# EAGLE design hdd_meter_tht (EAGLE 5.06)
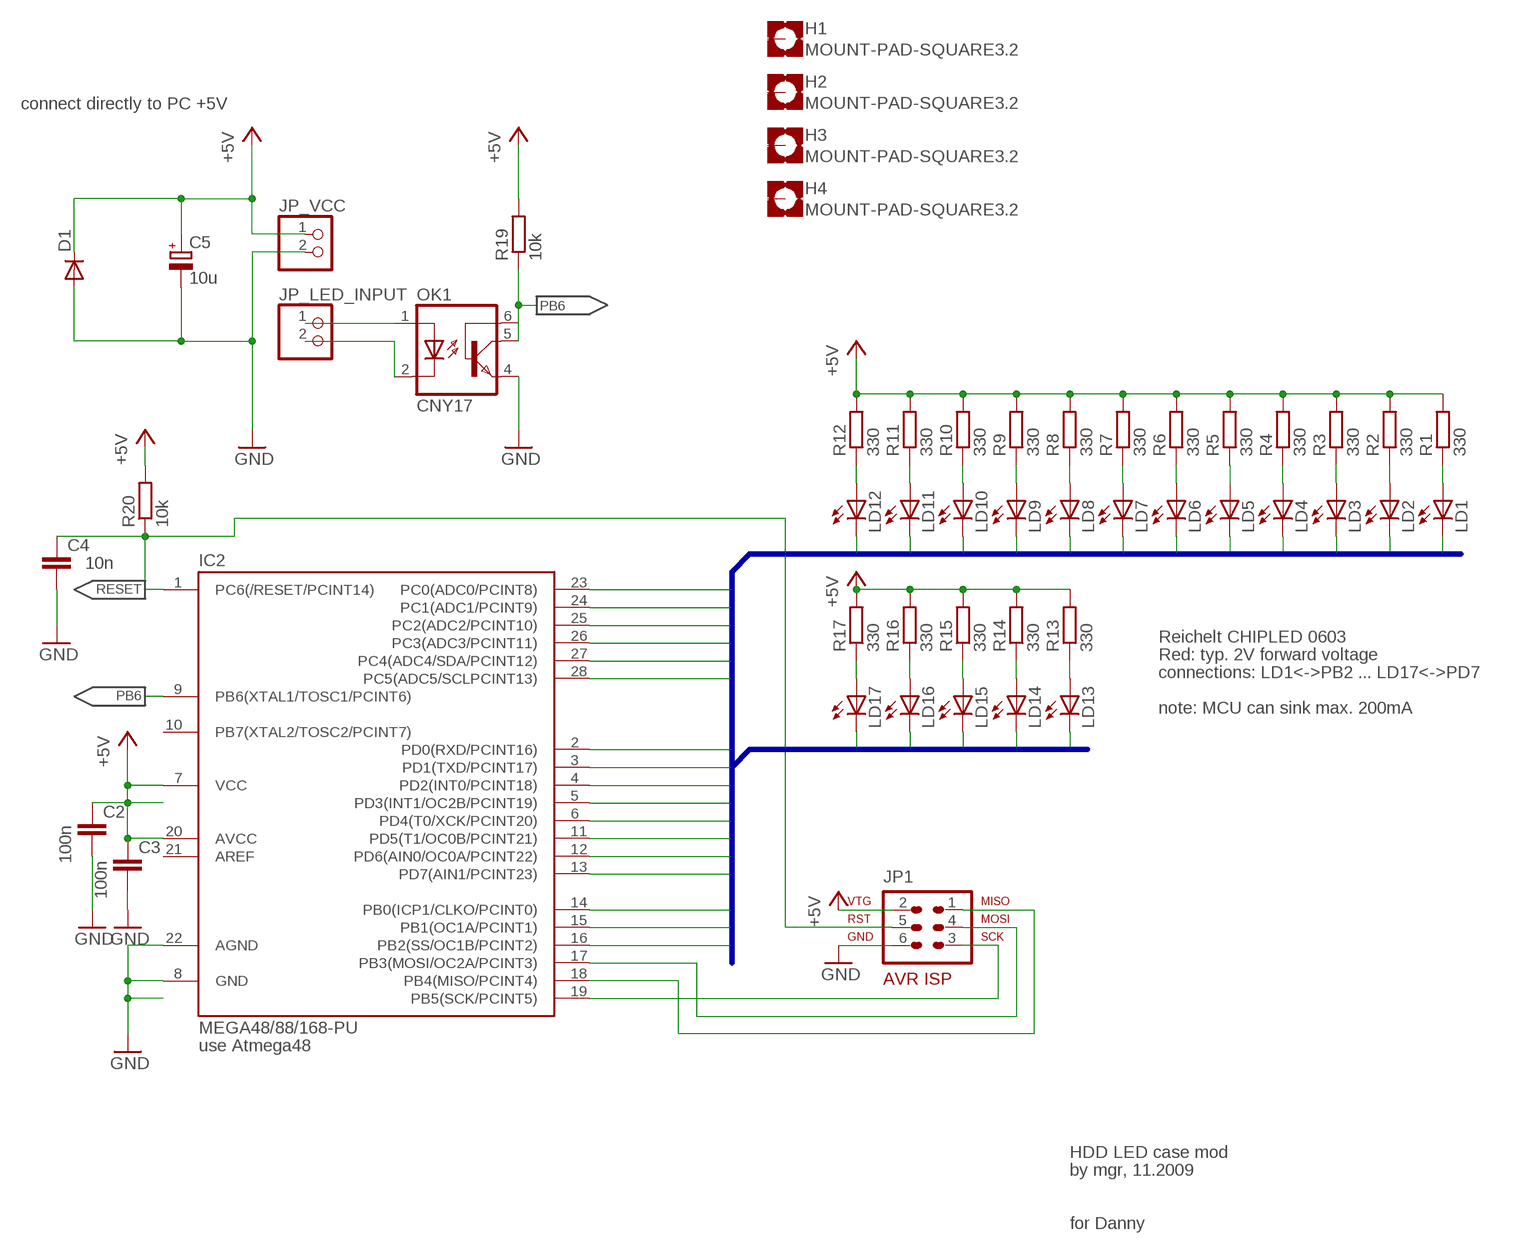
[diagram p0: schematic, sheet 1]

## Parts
C2  100n  C-EU050-024X044  [C050-024X044]
C3  100n  C-EU050-024X044  [C050-024X044]
C4  10n  C-EU050-024X044  [C050-024X044]
C5  10u  CPOL-EUE3.5-10  [E3,5-10]
D1  1N4148DO35-7  [DO35-7]
H1  MOUNT-PAD-SQUARE3.2  [3,2-PAD-SQUARE]
H2  MOUNT-PAD-SQUARE3.2  [3,2-PAD-SQUARE]
H3  MOUNT-PAD-SQUARE3.2  [3,2-PAD-SQUARE]
H4  MOUNT-PAD-SQUARE3.2  [3,2-PAD-SQUARE]
IC2  MEGA48/88/168-PU  [DIL28-3]
JP1  AVR-ISP-6  [AVR-ISP-6]
JP_LED_INPUT  PINHD-1X2  [1X02]
JP_VCC  PINHD-1X2  [1X02]
LD1  LED5MM  [LED5MM]
LD2  LED5MM  [LED5MM]
LD3  LED5MM  [LED5MM]
LD4  LED5MM  [LED5MM]
LD5  LED5MM  [LED5MM]
LD6  LED5MM  [LED5MM]
LD7  LED5MM  [LED5MM]
LD8  LED5MM  [LED5MM]
LD9  LED5MM  [LED5MM]
LD10  LED5MM  [LED5MM]
LD11  LED5MM  [LED5MM]
LD12  LED5MM  [LED5MM]
LD13  LED5MM  [LED5MM]
LD14  LED5MM  [LED5MM]
LD15  LED5MM  [LED5MM]
LD16  LED5MM  [LED5MM]
LD17  LED5MM  [LED5MM]
OK1  CNY17  [DIL06]
R1  330  R-EU_0207/7  [0207/7]
R2  330  R-EU_0207/7  [0207/7]
R3  330  R-EU_0207/7  [0207/7]
R4  330  R-EU_0207/7  [0207/7]
R5  330  R-EU_0207/7  [0207/7]
R6  330  R-EU_0207/7  [0207/7]
R7  330  R-EU_0207/7  [0207/7]
R8  330  R-EU_0207/7  [0207/7]
R9  330  R-EU_0207/7  [0207/7]
R10  330  R-EU_0207/7  [0207/7]
R11  330  R-EU_0207/7  [0207/7]
R12  330  R-EU_0207/7  [0207/7]
R13  330  R-EU_0207/7  [0207/7]
R14  330  R-EU_0207/7  [0207/7]
R15  330  R-EU_0207/7  [0207/7]
R16  330  R-EU_0207/7  [0207/7]
R17  330  R-EU_0207/7  [0207/7]
R19  10k  R-EU_0207/7  [0207/7]
R20  10k  R-EU_0207/7  [0207/7]

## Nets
+5V: C2.1 C3.1 C5.+ D1.C IC2.7(VCC) IC2.20(AVCC) JP1.2 JP_VCC.1 R1.2 R2.2 R3.2 R4.2 R5.2 R6.2 R7.2 R8.2 R9.2 R10.2 R11.2 R12.2 R13.2 R14.2 R15.2 R16.2 R17.2 R19.2 R20.2
GND: C2.2 C3.2 C4.2 C5.- D1.A IC2.8(GND) IC2.22(AGND) JP1.6 JP_VCC.2 OK1.4(EMI)
N$1: LD5.A R5.1
N$2: LD17.A R17.1
N$3: LD16.A R16.1
N$4: LD15.A R15.1
N$5: LD14.A R14.1
N$6: LD13.A R13.1
N$7: LD12.A R12.1
N$8: LD11.A R11.1
N$9: LD10.A R10.1
N$10: LD9.A R9.1
N$11: LD8.A R8.1
N$12: LD7.A R7.1
N$13: LD6.A R6.1
N$14: LD4.A R4.1
N$15: LD3.A R3.1
N$16: LD2.A R2.1
N$17: LD1.A R1.1
N$18: JP_LED_INPUT.1 OK1.1(A)
N$19: JP_LED_INPUT.2 OK1.2(C)
N$20: IC2.17(PB3(MOSI/OC2A/PCINT3)) JP1.4
N$21: IC2.18(PB4(MISO/PCINT4)) JP1.1
N$22: IC2.19(PB5(SCK/PCINT5)) JP1.3
PB0: IC2.14(PB0(ICP1/CLKO/PCINT0)) LD1.K(C)
PB1: IC2.15(PB1(OC1A/PCINT1)) LD2.K(C)
PB2: IC2.16(PB2(SS/OC1B/PCINT2)) LD3.K(C)
PB6: IC2.9(PB6(XTAL1/TOSC1/PCINT6)) OK1.5(COL) R19.1
PC0: IC2.23(PC0(ADC0/PCINT8)) LD4.K(C)
PC1: IC2.24(PC1(ADC1/PCINT9)) LD5.K(C)
PC2: IC2.25(PC2(ADC2/PCINT10)) LD6.K(C)
PC3: IC2.26(PC3(ADC3/PCINT11)) LD7.K(C)
PC4: IC2.27(PC4(ADC4/SDA/PCINT12)) LD8.K(C)
PC5: IC2.28(PC5(ADC5/SCLPCINT13)) LD9.K(C)
PD0: IC2.2(PD0(RXD/PCINT16)) LD10.K(C)
PD1: IC2.3(PD1(TXD/PCINT17)) LD11.K(C)
PD2: IC2.4(PD2(INT0/PCINT18)) LD12.K(C)
PD3: IC2.5(PD3(INT1/OC2B/PCINT19)) LD13.K(C)
PD4: IC2.6(PD4(T0/XCK/PCINT20)) LD14.K(C)
PD5: IC2.11(PD5(T1/OC0B/PCINT21)) LD15.K(C)
PD6: IC2.12(PD6(AIN0/OC0A/PCINT22)) LD16.K(C)
PD7: IC2.13(PD7(AIN1/PCINT23)) LD17.K(C)
RESET: C4.1 IC2.1(PC6(/RESET/PCINT14)) JP1.5 R20.1
Unconnected: H1.B3,2(MOUNT) H2.B3,2(MOUNT) H3.B3,2(MOUNT) H4.B3,2(MOUNT) IC2.10(PB7(XTAL2/TOSC2/PCINT7)) IC2.21(AREF) OK1.6(BAS)

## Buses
PB[0..2],PC[0..5],PD[0..7]

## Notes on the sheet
- connect directly to PC +5V
- Reichelt CHIPLED 0603
- Red: typ. 2V forward voltage
- connections: LD1<->PB2 ... LD17<->PD7
- note: MCU can sink max. 200mA
- use Atmega48
- HDD LED case mod
- by mgr, 11.2009
- for Danny

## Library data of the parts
C2-C4 = rcl:C-EU: CAPACITOR, European symbol
C5 = rcl:CPOL-EU: POLARIZED CAPACITOR, European symbol
D1 = diode:1N4148: DIODE
H1-H4 = holes:MOUNT-PAD-SQUARE: MOUNTING PAD, square
IC2 = avr-6:MEGA48/88/168-PU
JP1 = avr-6:AVR-ISP-6: AVR ISP-6 Serial Programming Header
JP_LED_INPUT JP_VCC = pinhead:PINHD-1X2: PIN HEADER
LD1-LD17 = led:LED: LED
OK1 = optocoupler-2:CNY17: SIEMENS OPTO COUPLER
R1-R17 R19 R20 = rcl:R-EU_: RESISTOR, European symbol

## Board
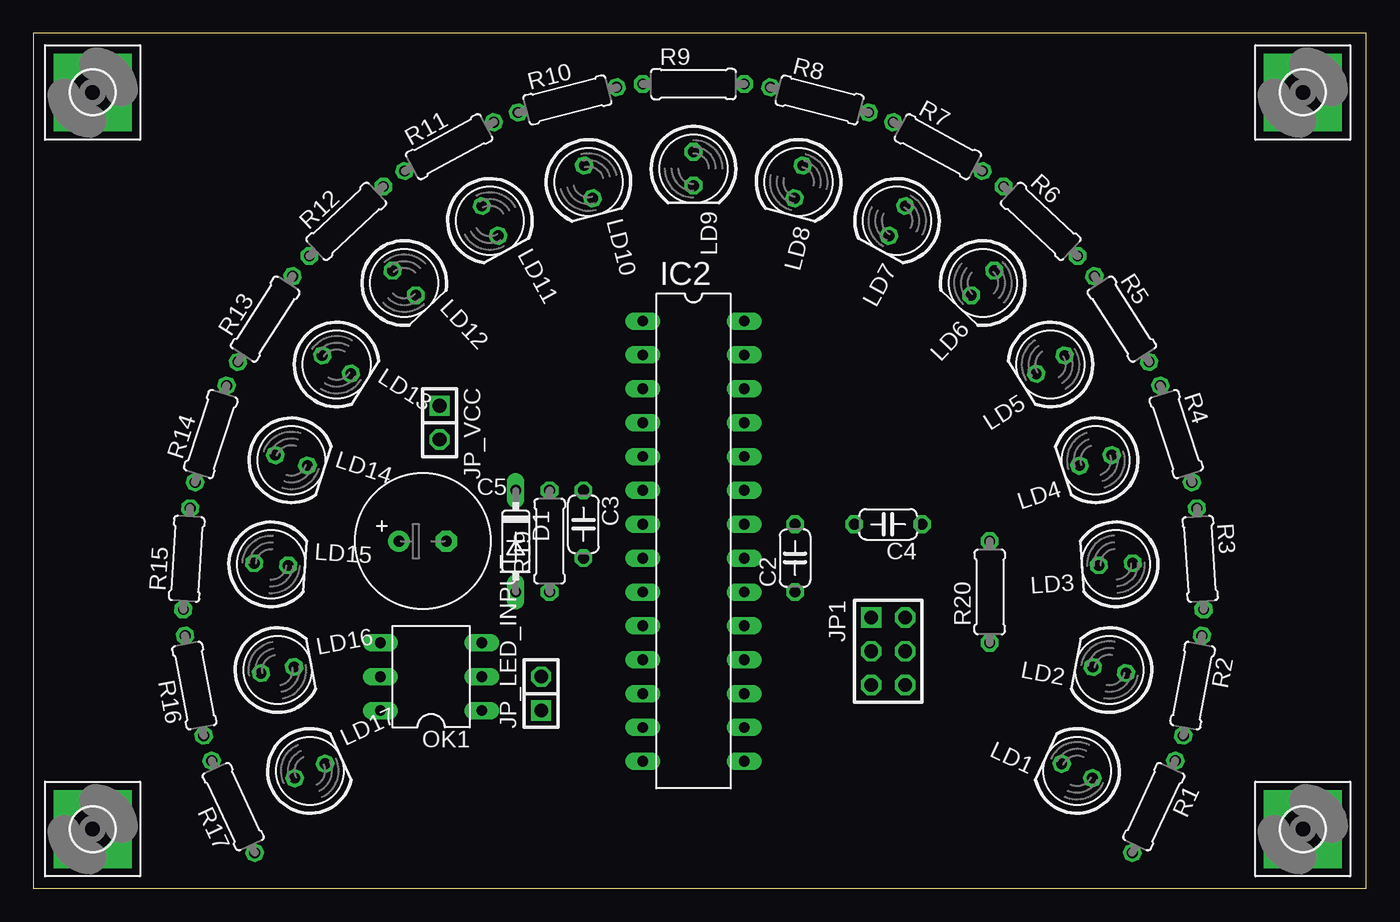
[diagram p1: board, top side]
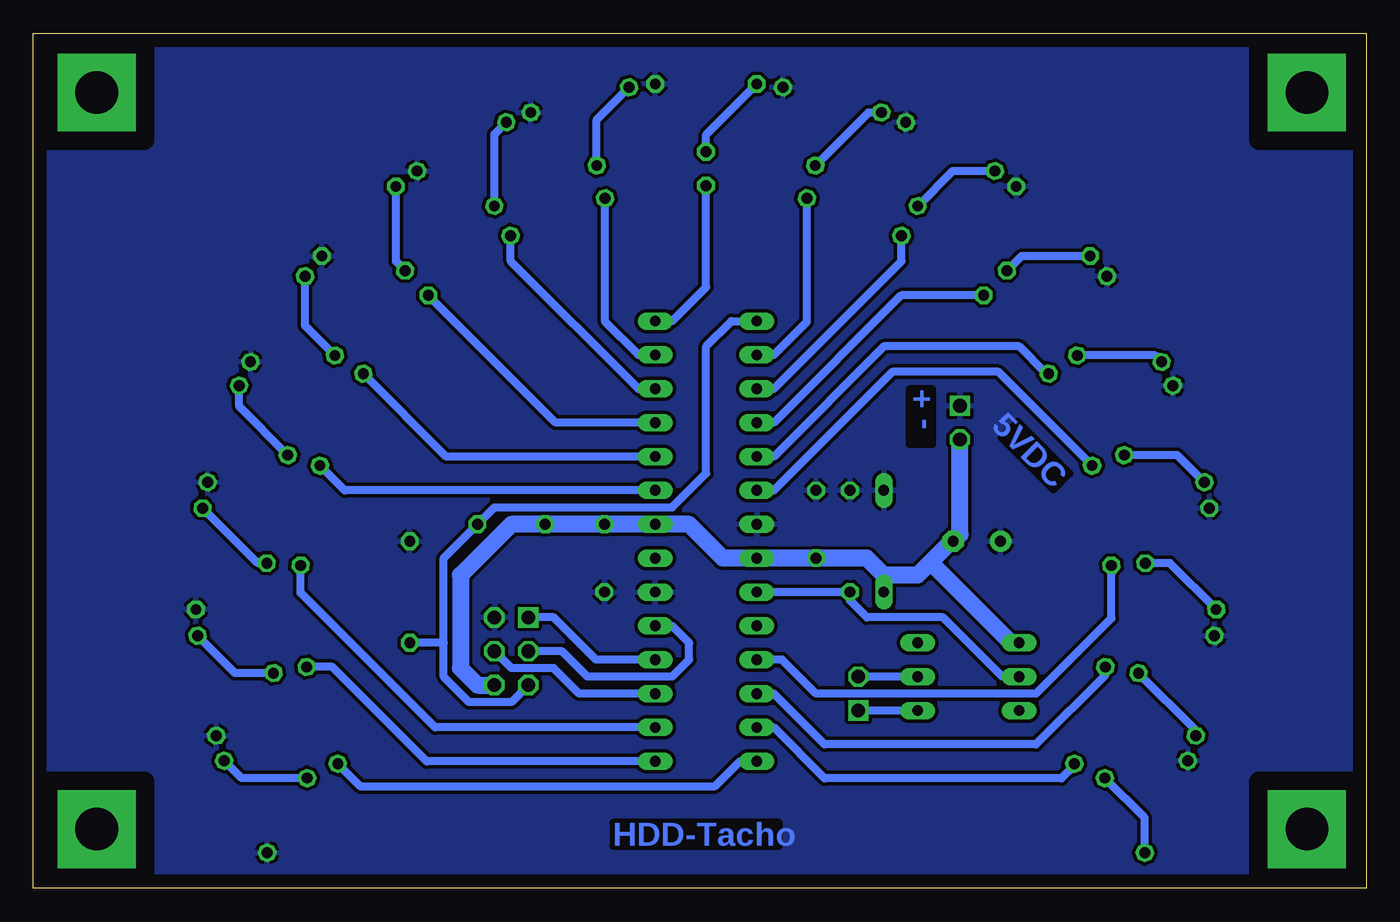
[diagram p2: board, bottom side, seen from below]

Size 100 x 64.12 mm. Coordinates in mm from the lower left corner, seen from the top.
Outline: 0,0 100,0 100,64.12 0,64.12 0,0
Copper layers (1*16): Top 0.035mm / dielectric 1.5mm / Bottom 0.035mm
Design rules "default *": minimum track width 10mil, minimum drill 24mil, track to track 8mil, track to pad 8mil, pad to pad 8mil, via to via 8mil, smd to smd 8mil, copper to edge 40mil, drill to drill 8mil, minimum pad ring 10mil, minimum via ring 8mil, stop-mask expansion 4mil, vias tented up to drill 0mil, thermal gap 10mil

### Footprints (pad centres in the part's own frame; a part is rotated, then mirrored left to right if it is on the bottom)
C050-024X044 = drill 0.813 octagon: 1 -2.54,0; 2 2.54,0
E3,5-10 = drill 0.813 pad 1.6 round: + -1.778,0 | drill 0.813 pad 1.6 octagon: - 1.778,0
DO35-7 = drill 0.813 long: A 3.81,0; C -3.81,0
3,2-PAD-SQUARE = drill 3.2 pad 5.842 square: B3,2 0,0
DIL28-3 = drill 0.813 long: 1 -16.51,-3.81; 2 -13.97,-3.81; 3 -11.43,-3.81; 4 -8.89,-3.81; 5 -6.35,-3.81; 6 -3.81,-3.81; 7 -1.27,-3.81; 8 1.27,-3.81; 9 3.81,-3.81; 10 6.35,-3.81; 11 8.89,-3.81; 12 11.43,-3.81; 13 13.97,-3.81; 14 16.51,-3.81; 15 16.51,3.81; 16 13.97,3.81; 17 11.43,3.81; 18 8.89,3.81; 19 6.35,3.81; 20 3.81,3.81; 21 1.27,3.81; 22 -1.27,3.81; 23 -3.81,3.81; 24 -6.35,3.81; 25 -8.89,3.81; 26 -11.43,3.81; 27 -13.97,3.81; 28 -16.51,3.81
AVR-ISP-6 = drill 1.016 square: 1 -2.54,-1.27 | drill 1.016 octagon: 2 -2.54,1.27; 3 0,-1.27; 4 0,1.27; 5 2.54,-1.27; 6 2.54,1.27
1X02 = drill 1.016 square: 1 -1.27,0 | drill 1.016 octagon: 2 1.27,0
LED5MM = drill 0.813 octagon: A -1.27,0; K 1.27,0
DIL06 = drill 0.813 long: 1 -2.54,-3.81; 2 0,-3.81; 3 2.54,-3.81; 4 2.54,3.81; 5 0,3.81; 6 -2.54,3.81
0207/7 = drill 0.813 octagon: 1 -3.81,0; 2 3.81,0

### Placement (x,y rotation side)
C2  57.15,24.77 90 top
C3  41.27,27.3 270 top
C4  64.14,27.3 180 top
C5  29.21,26.04 0 top
D1  36.2,26.04 270 top
H1  4.45,4.45 0 top
H2  4.45,59.69 0 top
H3  95.25,59.69 0 top
H4  95.25,4.45 0 top
IC2  49.53,26.04 270 top
JP1  64.14,17.78 270 top
JP_LED_INPUT  38.1,14.61 90 top
JP_VCC  30.48,34.92 270 top
LD1  78.31,8.81 155 top
LD2  80.74,16.37 169.4 top
LD3  81.21,24.3 183.8 top
LD4  79.7,32.1 198.1 top
LD5  76.31,39.28 212.5 top
LD6  71.23,45.4 226.8 top
LD7  64.8,50.06 241.3 top
LD8  57.41,52.98 255.6 top
LD9  49.53,53.98 270 top
LD10  41.65,52.98 284.4 top
LD11  34.26,50.06 298.7 top
LD12  27.83,45.4 313.2 top
LD13  22.75,39.28 327.5 top
LD14  19.36,32.1 341.9 top
LD15  17.85,24.3 356.2 top
LD16  18.32,16.37 10.6 top
LD17  20.75,8.81 25 top
OK1  29.84,15.88 90 top
R1  84.06,6.12 245 top
R2  86.98,15.2 259.4 top
R3  87.55,24.72 273.8 top
R4  85.74,34.08 288.1 top
R5  81.66,42.7 302.5 top
R6  75.57,50.03 316.8 top
R7  67.86,55.63 331.3 top
R8  58.99,59.13 345.6 top
R9  49.53,60.33 0 top
R10  40.07,59.13 14.4 top
R11  31.2,55.63 28.7 top
R12  23.49,50.03 43.2 top
R13  17.4,42.7 57.5 top
R14  13.32,34.08 71.9 top
R15  11.51,24.72 86.2 top
R16  12.08,15.2 100.6 top
R17  15,6.12 115 top
R19  38.73,26.04 90 top
R20  71.75,22.23 90 top

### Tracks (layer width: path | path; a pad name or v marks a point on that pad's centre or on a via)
+5V
  pour Bottom (isolate 0.254): -5.71,71.12 108.58,71.12 108.58,-5.71 -5.71,-5.71
GND
  Bottom 1.27: 36.2,23.5 37.47,24.77 C3.2 IC2.8 48.26,24.77 50.8,27.3 IC2.22 C2.2 C4.2 64.14,27.3 67.94,23.5 67.94,16.51 66.67,15.24 JP1.6 | 36.2,23.5 D1.A | JP_VCC.2 30.48,26.54 C5.- 31.11,26.04 32.7,24.45 | 32.7,24.45 33.66,23.5 36.2,23.5 | OK1.4 26.67,18.41 32.7,24.45
N$1
  Bottom 0.61: R5.1 79.62,42.2 LD5.A
N$2
  Bottom 0.61: R17.1 16.61,5.28 LD17.A
N$3
  Bottom 0.61: R16.1 12.78,11.85 LD16.A
N$4
  Bottom 0.61: LD15.A 14.73,24.39 R15.1
N$5
  Bottom 0.61: LD14.A 14.18,32.5 R14.1
N$6
  Bottom 0.61: LD13.A 15.83,39.97 R13.1
N$7
  Bottom 0.61: R12.1 25.86,47.42 LD12.A
N$8
  Bottom 0.61: R11.1 31.02,53.8 LD11.A
N$9
  Bottom 0.61: R10.1 37.36,58.18 LD10.A
N$10
  Bottom 0.61: LD9.A 49.53,56.52 R9.1
N$11
  Bottom 0.61: LD8.A 57.73,57.65 R8.1
N$12
  Bottom 0.61: LD7.A 65.41,56.56 R7.1
N$13
  Bottom 0.61: R6.1 72.8,47.02 LD6.A
N$14
  Bottom 0.61: R4.1 84.56,36.14 LD4.A
N$15
  Bottom 0.61: LD3.A 83.16,24.39 R3.1
N$16
  Bottom 0.61: LD2.A 84.87,16.14 R2.1
N$17
  Bottom 0.61: LD1.A 84.36,8.27 R1.1
N$18
  Bottom 0.61: OK1.1 JP_LED_INPUT.1
N$19
  Bottom 0.61: OK1.2 JP_LED_INPUT.2
N$20
  Bottom 0.61: IC2.17 59.05,14.61 60.96,16.51 64.14,16.51 JP1.4
N$21
  Bottom 0.61: IC2.18 57.78,17.14 60.96,20.32 JP1.1
N$22
  Bottom 0.61: IC2.19 52.07,19.68 50.8,18.41 50.8,17.14 52.07,15.88 58.42,15.88 60.33,17.78 JP1.3
PB0
  Bottom 0.61: IC2.14 46.99,9.53 48.9,7.62 75.43,7.62 LD1.K
PB1
  Bottom 0.61: LD2.K 77.56,16.61 70.48,9.53 IC2.15
PB2
  Bottom 0.61: IC2.16 69.85,12.06 79.94,22.16 LD3.K
PB6
  Bottom 0.61: IC2.9 R19.1 38.73,21.59 37.47,20.32 31.75,20.32 27.3,15.88 OK1.5
PC0
  Bottom 0.61: IC2.23 76.64,29.84 LD4.K
PC1
  Bottom 0.61: IC2.24 69.02,32.38 LD5.K
PC2
  Bottom 0.61: IC2.25 60.82,34.92 LD6.K
PC3
  Bottom 0.61: LD7.K 64.19,47.05 54.61,37.47 IC2.26
PC4
  Bottom 0.61: LD8.K 57.1,42.49 54.61,40.01 IC2.27
PC5
  Bottom 0.61: LD9.K 49.53,45.09 52.07,42.55 IC2.28
PD0
  Bottom 0.61: LD10.K 41.96,42.49 44.45,40.01 IC2.2
PD1
  Bottom 0.61: LD11.K 34.87,47.05 44.45,37.47 IC2.3
PD2
  Bottom 0.61: LD12.K 34.9,44.47 44.45,34.92 IC2.4
PD3
  Bottom 0.61: LD13.K 24,38.6 26.04,40.64 36.2,40.64 44.45,32.38 IC2.5
PD4
  Bottom 0.61: IC2.6 44.45,29.84 35.56,38.73 27.59,38.73 LD14.K
PD5
  Bottom 0.61: IC2.11 43.81,17.14 41.27,14.61 24.77,14.61 19.11,20.25 LD15.K
PD6
  Bottom 0.61: LD16.K 19.57,15.99 24.77,10.79 40.64,10.79 44.45,14.61 IC2.12
PD7
  Bottom 0.61: IC2.13 44.45,12.06 40.64,8.26 22.86,8.26 21.91,9.21 LD17.K
RESET
  Bottom 0.61: IC2.1 47.62,42.55 49.53,40.64 49.53,31.11 52.07,28.57 65.41,28.57 C4.1 69.22,24.77 69.22,18.41 | 69.22,18.41 69.22,15.88 67.31,13.97 64.14,13.97 JP1.5 | 69.22,18.41 R20.1

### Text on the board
Bottom: - + | 5VDC | HDD-Tacho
